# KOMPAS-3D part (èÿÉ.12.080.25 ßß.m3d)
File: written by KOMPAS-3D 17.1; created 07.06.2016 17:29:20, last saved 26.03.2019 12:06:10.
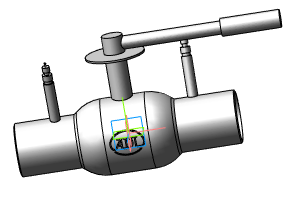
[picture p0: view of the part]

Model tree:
1. Операция без истории:5  (labels: Сталь 20  ГОСТ 1050-88)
